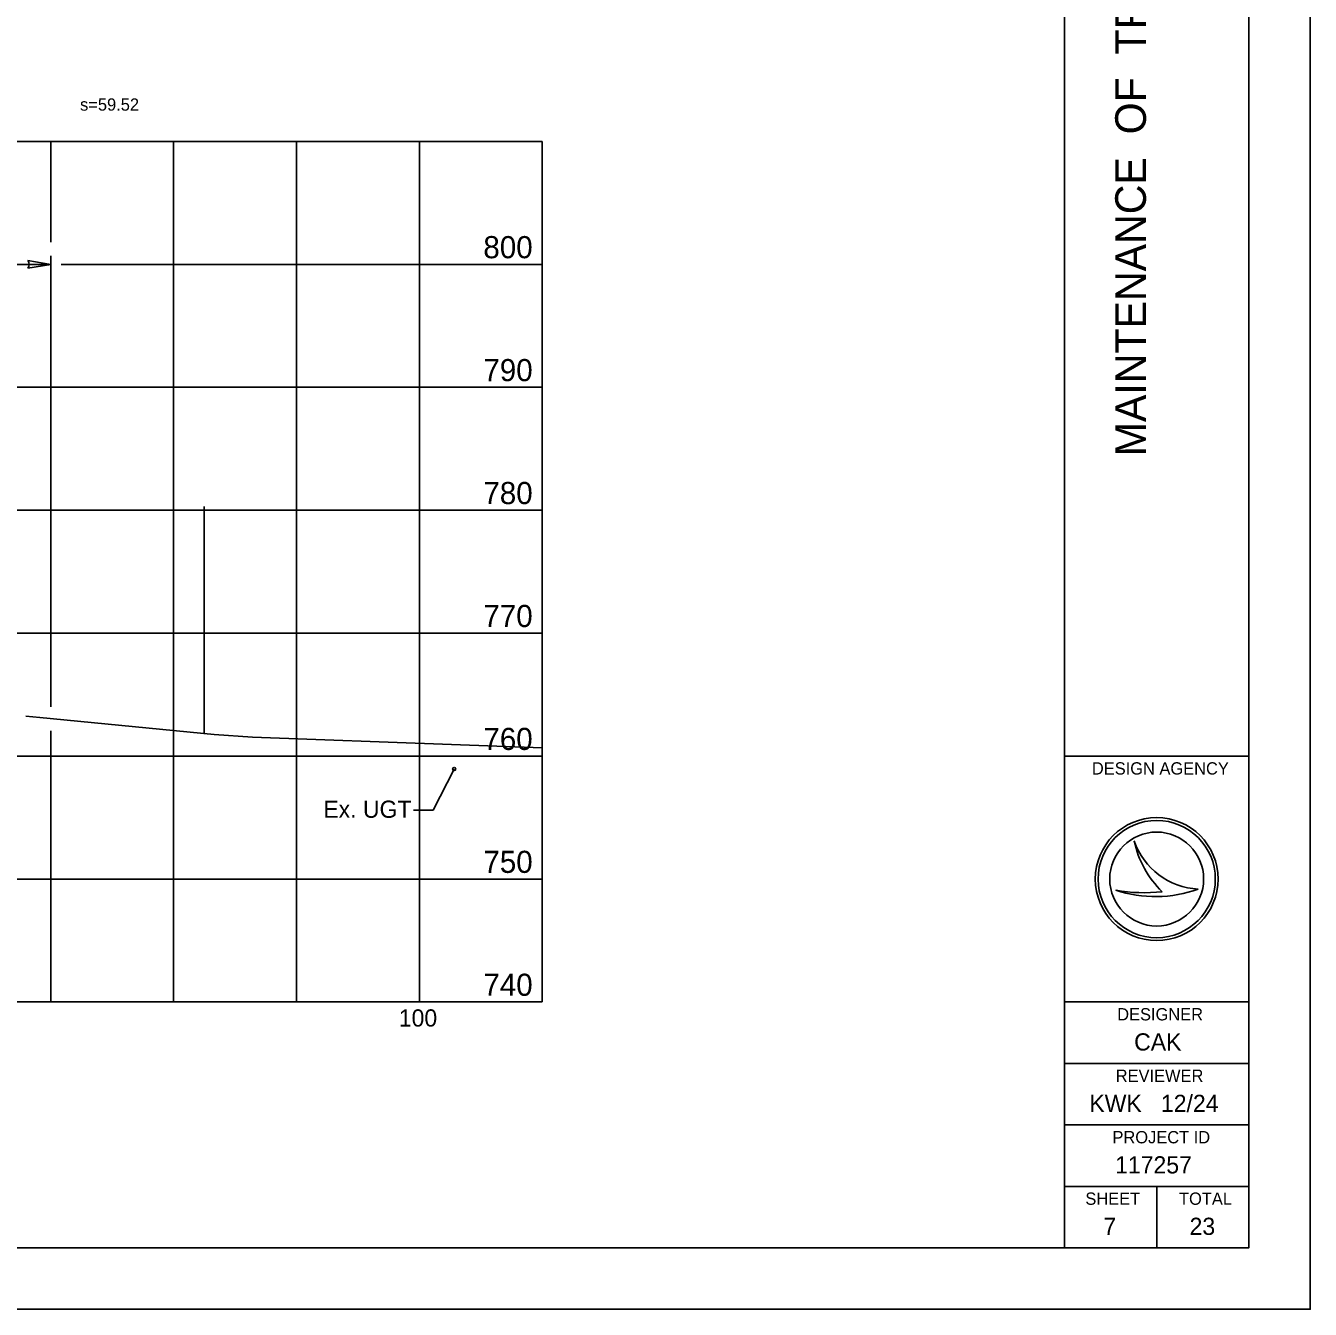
# Model space of a CAD drawing. Extents: x -1395 to 1843, y -1176 to 1887.
# Drawn here: x 470.9 to 680, y -880 to -671.2 of the extents above; entities that cross this region are included whole.
import ezdxf

# ---------------------------------------------------------------- set-up
doc = ezdxf.new("R2010")
doc.units = 0
for name, color, linetype in [('Default', 7, 'Continuous'), ('GE_X_Alignment', 7, 'Continuous'), ('HY_X_Water_Edge', 7, 'Continuous'), ('PV_X_EOP', 7, 'Continuous'), ('RD_X_GR_Lt', 7, 'Continuous'), ('RW_P_Esmt_TMP', 7, 'Continuous'), ('SH_Border', 7, 'Continuous'), ('SH_Cut_Line', 7, 'Continuous'), ('SH_Data', 7, 'Continuous'), ('SH_Major_Grid_Line', 7, 'Continuous'), ('SH_Named_Boundary', 7, 'Continuous'), ('SV_X_Break_Lines', 7, 'Continuous')]:
    doc.layers.add(name, color=color, linetype=linetype)

msp = doc.modelspace()

# ---------------------------------------------------------------- linework, layer by layer
at = {"layer": 'Default'}
for p, q in [((475, -710), (471.29, -709.38)), ((471.29, -709.38), (471.29, -709.38)), ((471.3, -710.62), (475, -710)), ((471.3, -710.62), (471.3, -710.62))]:
    msp.add_line(p, q, dxfattribs=at)
msp.add_arc((470.36, -710.01), 1.12, 327.1412, 33.822, dxfattribs=at)
at = {"layer": 'GE_X_Alignment'}
for p, q in [((115, -690), (555, -690)), ((475, -782.01), (475, -708.61)), ((540.66, -792.1), (537.25, -798.77)), ((537.25, -798.77), (534.06, -798.77))]:
    msp.add_line(p, q, dxfattribs=at)
at = {"layer": 'HY_X_Water_Edge'}
msp.add_lwpolyline([(470.93, -783.52), (473.24, -783.73), (501.62, -786.48), (507.82, -786.93), (540.21, -788.09), (555, -788.63)], dxfattribs=at)
at = {"layer": 'RD_X_GR_Lt'}
msp.add_circle((540.66, -792.1), 0.25, dxfattribs=at)
at = {"layer": 'RW_P_Esmt_TMP'}
for p, q in [((475, -706.4), (475, -690)), ((495, -830), (495, -690)), ((515, -830), (515, -690)), ((535, -830), (535, -690)), ((555, -830), (555, -690)), ((476.69, -710), (555, -710)), ((115, -730), (555, -730)), ((115, -750), (555, -750)), ((115, -770), (555, -770)), ((475, -830), (475, -785.89)), ((115, -790), (555, -790)), ((115, -810), (555, -810)), ((115, -830), (555, -830))]:
    msp.add_line(p, q, dxfattribs=at)
at = {"layer": 'SH_Border'}
msp.add_lwpolyline([(0, -880), (680, -880), (680, -440), (0, -440)], close=True, dxfattribs=at)
at = {"layer": 'SH_Cut_Line'}
for p, q in [((640, -870), (640, -450)), ((640, -790), (670, -790)), ((640, -830), (670, -830)), ((640, -840), (670, -840)), ((640, -850), (670, -850)), ((640, -860), (670, -860))]:
    msp.add_line(p, q, dxfattribs=at)
msp.add_lwpolyline([(30, -450), (670, -450), (670, -870), (30, -870)], close=True, dxfattribs=at)
at = {"layer": 'SH_Major_Grid_Line'}
msp.add_line((475, -710), (335, -710), dxfattribs=at)
at = {"layer": 'SH_Named_Boundary'}
for p, q in [((651.35, -803.81), (651.35, -803.81)), ((655, -810), (655, -810)), ((648.34, -811.81), (648.34, -811.81)), ((661.75, -811.63), (661.75, -811.63)), ((655, -870), (655, -860)), ((647.5, -866.5), (647.5, -866.5))]:
    msp.add_line(p, q, dxfattribs=at)
for radius in [10, 9.54, 9.54, 7.64]:
    msp.add_circle((655, -810), radius, dxfattribs=at)
for centre, radius, start, end in [((662.32, -800.05), 11.6, 198.9257, 198.9319), ((666.93, -800.6), 15.91, 191.6379, 191.6421), ((662.32, -800.05), 11.6, 198.9319, 267.1657), ((666.93, -800.6), 15.91, 191.6421, 226.0947), ((654.79, -792.6), 20.26, 251.4576, 290.0832), ((652.96, -786.91), 25.32, 259.4964, 259.4995), ((654.79, -792.6), 20.26, 251.4527, 251.4576), ((652.96, -786.91), 25.32, 259.4995, 276.6672)]:
    msp.add_arc(centre, radius, start, end, dxfattribs=at)
at = {"layer": 'SV_X_Break_Lines'}
msp.add_line((500, -786.32), (500, -749.4), dxfattribs=at)

# ---------------------------------------------------------------- texts
at = {"layer": 'PV_X_EOP'}
msp.add_text('s=59.52', height=2, dxfattribs=at).set_placement((479.78, -684.99))
at = {"layer": 'SH_Data'}
for s, height, p in [('800', 3.6, (545.41, -709)), ('790', 3.6, (545.41, -729)), ('780', 3.6, (545.41, -749)), ('770', 3.6, (545.41, -769)), ('760', 3.6, (545.41, -789)), ('Ex. UGT', 2.8, (519.36, -800.04)), ('750', 3.6, (545.41, -809)), ('740', 3.6, (545.41, -829)), ('100', 2.8, (531.65, -834))]:
    msp.add_text(s, height=height, dxfattribs=at).set_placement(p)
at = {"layer": 'SH_Named_Boundary'}
msp.add_text('MAINTENANCE  OF  TRAFFIC  -  TRANSVERSE SECTIONS', height=5, rotation=90, dxfattribs=at).set_placement((653.25, -741.22))
for s, height, p in [('DESIGN AGENCY', 2, (644.45, -793)), ('DESIGNER', 2, (648.57, -833)), ('CAK', 2.8, (651.33, -837.9)), ('REVIEWER', 2, (648.33, -843)), ('KWK   12/24', 2.8, (644.04, -847.9)), ('PROJECT ID', 2, (647.8, -853)), ('117257', 2.8, (648.23, -857.9)), ('SHEET', 2, (643.39, -863)), ('TOTAL', 2, (658.63, -863)), ('7', 2.8, (646.32, -867.9)), ('23', 2.8, (660.35, -867.9))]:
    msp.add_text(s, height=height, dxfattribs=at).set_placement(p)

doc.saveas('drawing.dxf')
